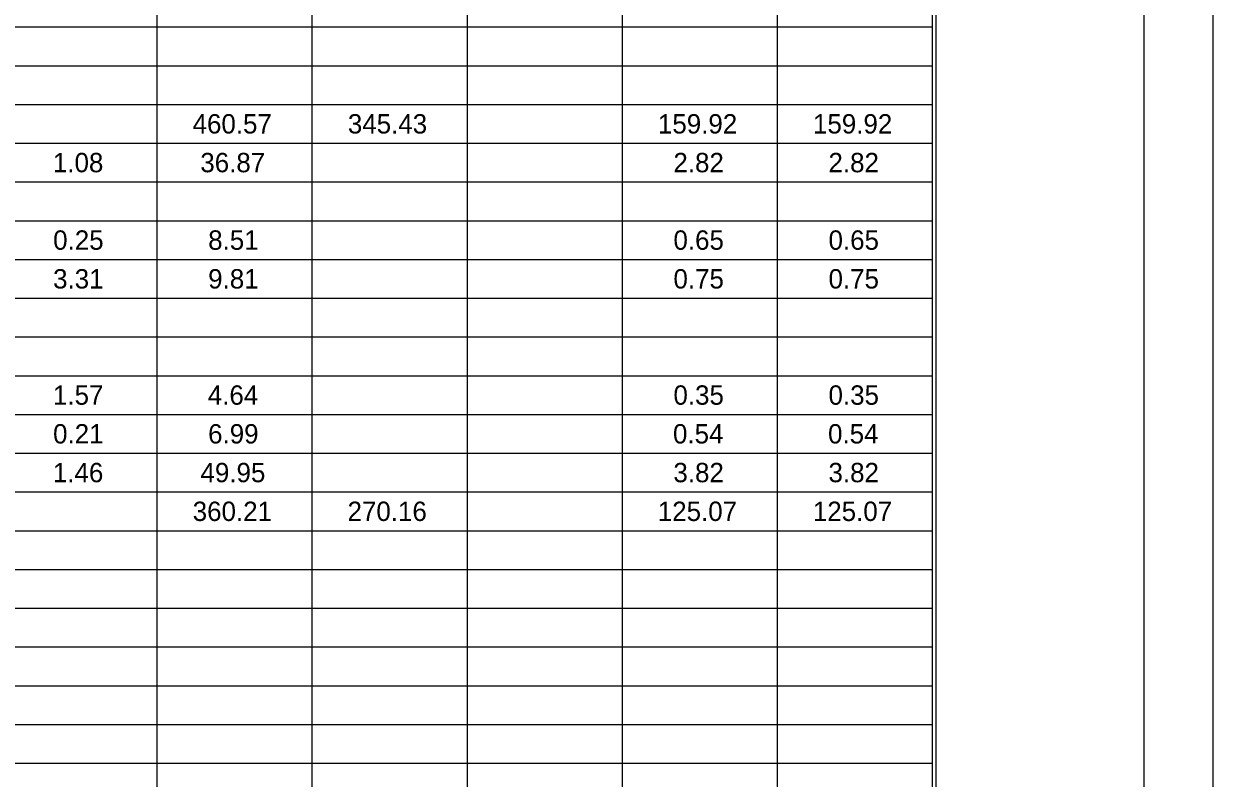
# Model space of a CAD drawing. Extents: x 0 to 34, y 0 to 22.
# Drawn here: x 25.41 to 34, y 5.43 to 10.88 of the extents above; entities that cross this region are included whole.
import ezdxf

# ---------------------------------------------------------------- set-up
doc = ezdxf.new("R2010")
doc.units = 0
for name, color, linetype in [('SH_Border', 7, 'Continuous'), ('SH_Cut_Line', 7, 'Continuous'), ('SH_Data', 7, 'Continuous'), ('SH_Text', 7, 'Continuous')]:
    doc.layers.add(name, color=color, linetype=linetype)

msp = doc.modelspace()

# ---------------------------------------------------------------- linework, layer by layer
at = {"layer": 'SH_Border'}
msp.add_line((32, 0.5), (32, 21.5), dxfattribs=at)
msp.add_lwpolyline([(1.5, 21.5), (33.5, 21.5), (33.5, 0.5), (1.5, 0.5)], close=True, dxfattribs=at)
at = {"layer": 'SH_Cut_Line'}
msp.add_lwpolyline([(0, 0), (34, 0), (34, 22), (0, 22)], close=True, dxfattribs=at)
at = {"layer": 'SH_Data'}
for p, q in [((26.3706, 21.5), (26.3706, 0.5)), ((27.4906, 21.5), (27.4906, 0.78)), ((28.6106, 21.5), (28.6106, 0.5)), ((29.7306, 21.5), (29.7306, 0.5)), ((30.8506, 21.5), (30.8506, 0.5)), ((31.9706, 21.5), (31.9706, 0.5)), ((1.5, 10.86), (31.9706, 10.86)), ((1.5, 10.58), (31.9706, 10.58)), ((1.5, 10.3), (31.9706, 10.3)), ((1.5, 10.02), (31.9706, 10.02)), ((1.5, 9.74), (31.9706, 9.74)), ((1.5, 9.46), (31.9706, 9.46)), ((1.5, 9.18), (31.9706, 9.18)), ((1.5, 8.9), (31.9706, 8.9)), ((1.5, 8.62), (31.9706, 8.62)), ((1.5, 8.34), (31.9706, 8.34)), ((1.5, 8.06), (31.9706, 8.06)), ((1.5, 7.78), (31.9706, 7.78)), ((1.5, 7.5), (31.9706, 7.5)), ((1.5, 7.22), (31.9706, 7.22)), ((1.5, 6.94), (31.9706, 6.94)), ((1.5, 6.66), (31.9706, 6.66)), ((1.5, 6.38), (31.9706, 6.38)), ((1.5, 6.1), (31.9706, 6.1)), ((1.5, 5.82), (31.9706, 5.82)), ((1.5, 5.54), (31.9706, 5.54))]:
    msp.add_line(p, q, dxfattribs=at)

# ---------------------------------------------------------------- texts
at = {"layer": 'SH_Text'}
for s, p in [('460.57', (26.6285, 10.09)), ('345.43', (27.7501, 10.09)), ('159.92', (29.9895, 10.09)), ('159.92', (31.1095, 10.09)), ('1.08', (25.6197, 9.81)), ('36.87', (26.6843, 9.81)), ('2.82', (30.1012, 9.81)), ('2.82', (31.2212, 9.81)), ('0.25', (25.6216, 9.25)), ('8.51', (26.7411, 9.25)), ('0.65', (30.1016, 9.25)), ('0.65', (31.2216, 9.25)), ('3.31', (25.6211, 8.97)), ('9.81', (26.7411, 8.97)), ('0.75', (30.1016, 8.97)), ('0.75', (31.2216, 8.97)), ('1.57', (25.6202, 8.13)), ('4.64', (26.7383, 8.13)), ('0.35', (30.1016, 8.13)), ('0.35', (31.2216, 8.13)), ('0.21', (25.6211, 7.85)), ('6.99', (26.7407, 7.85)), ('0.54', (30.0983, 7.85)), ('0.54', (31.2183, 7.85)), ('1.46', (25.6195, 7.57)), ('49.95', (26.6857, 7.57)), ('3.82', (30.1012, 7.57)), ('3.82', (31.2212, 7.57)), ('360.21', (26.6294, 7.29)), ('270.16', (27.7477, 7.29)), ('125.07', (29.9885, 7.29)), ('125.07', (31.1085, 7.29))]:
    msp.add_text(s, height=0.14, dxfattribs=at).set_placement(p)

doc.saveas('drawing.dxf')
